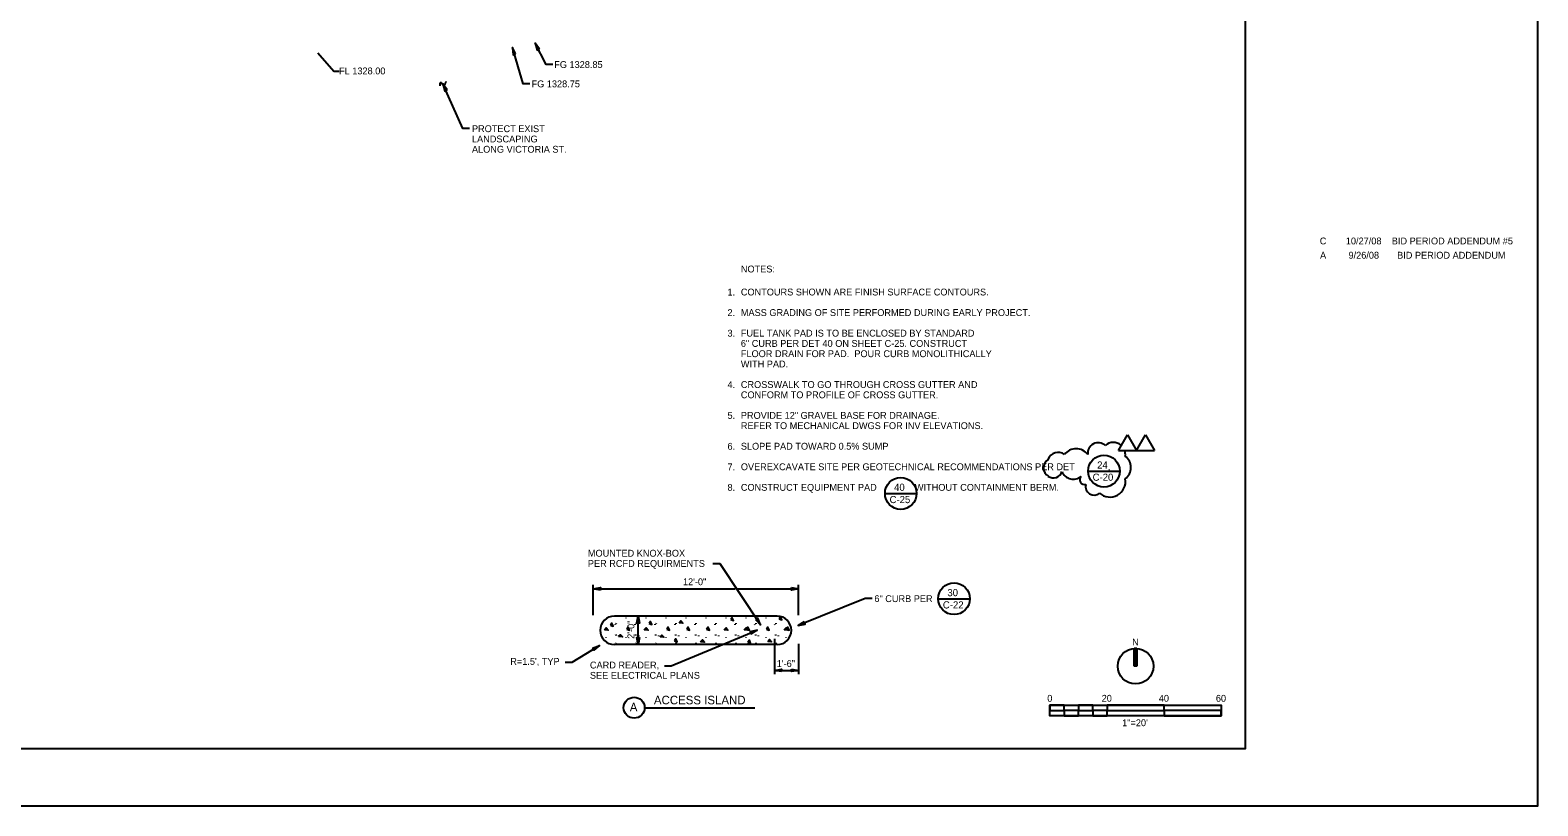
# Model space of a CAD drawing. Extents: x 0 to 3.5, y 0 to 3.39.
# Drawn here: x 1.299 to 3.5, y 0 to 1.132 of the extents above; entities that cross this region are included whole.
import ezdxf

# ---------------------------------------------------------------- set-up
doc = ezdxf.new("R2010")
doc.units = 0
for name, color, linetype in [('C-MARK', 7, 'Continuous'), ('C-PATT', 7, 'Continuous'), ('C-REVC', 7, 'Continuous'), ('C-TEXT', 7, 'Continuous'), ('G-SYMB', 7, 'Continuous'), ('G-TEXT', 7, 'Continuous'), ('G-TTLB-OTLN', 7, 'Continuous'), ('G-TTLB-VIEW', 7, 'Continuous')]:
    doc.layers.add(name, color=color, linetype=linetype)

msp = doc.modelspace()

# ---------------------------------------------------------------- linework, layer by layer
at = {"layer": 'C-MARK'}
for p, q in [((2.1211, 0.2782), (2.1211, 0.3225)), ((2.1211, 0.3167), (2.3284, 0.3167)), ((2.3318, 0.3167), (2.4209, 0.3167)), ((2.4209, 0.2782), (2.4209, 0.3225)), ((2.1868, 0.2353), (2.1868, 0.277)), ((2.2011, 0.2766), (2.2011, 0.277)), ((2.3856, 0.2436), (2.3856, 0.192)), ((2.4209, 0.2363), (2.4209, 0.192)), ((2.3856, 0.1977), (2.4209, 0.1977))]:
    msp.add_line(p, q, dxfattribs=at)
for points in [[(2.0287, 1.0536), (2.0187, 1.0536), (2.0031, 1.1065)], [(2.0623, 1.0815), (2.0523, 1.0815), (2.0364, 1.1127)], [(1.719, 1.0988), (1.7423, 1.0719), (1.7503, 1.0719)], [(1.9407, 0.9882), (1.9307, 0.9882), (1.9018, 1.0533)], [(2.2957, 0.3536), (2.3057, 0.3536), (2.3655, 0.2643)], [(2.5282, 0.3025), (2.5182, 0.3025), (2.4201, 0.2632)], [(2.2251, 0.2045), (2.2351, 0.2045), (2.3605, 0.2561)], [(2.0803, 0.2095), (2.0903, 0.2095), (2.1301, 0.234)]]:
    msp.add_lwpolyline(points, dxfattribs=at)
msp.add_open_spline([(1.8975, 1.0504), (1.8976, 1.0586), (1.9039, 1.048), (1.9064, 1.0571)], degree=2, dxfattribs=at)
at = {"layer": 'C-PATT'}
for p, q in [((2.1521, 0.277), (2.3896, 0.277)), ((2.1534, 0.264), (2.1532, 0.265)), ((2.1548, 0.2658), (2.155, 0.2664)), ((2.1585, 0.2762), (2.1585, 0.277)), ((2.1694, 0.2739), (2.1694, 0.2744)), ((2.1825, 0.264), (2.1823, 0.265)), ((2.1839, 0.2658), (2.1841, 0.2664)), ((2.1877, 0.2762), (2.1877, 0.277)), ((2.1985, 0.2739), (2.1985, 0.2744)), ((2.2117, 0.264), (2.2115, 0.265)), ((2.2131, 0.2658), (2.2133, 0.2664)), ((2.2168, 0.2762), (2.2168, 0.277)), ((2.2277, 0.2739), (2.2277, 0.2744)), ((2.2408, 0.264), (2.2406, 0.265)), ((2.2422, 0.2658), (2.2424, 0.2664)), ((2.246, 0.2762), (2.246, 0.277)), ((2.2568, 0.2739), (2.2568, 0.2744)), ((2.27, 0.264), (2.2698, 0.265)), ((2.2714, 0.2658), (2.2716, 0.2664)), ((2.2751, 0.2762), (2.2751, 0.277)), ((2.286, 0.2739), (2.286, 0.2744)), ((2.2991, 0.264), (2.2989, 0.265)), ((2.3005, 0.2658), (2.3007, 0.2664)), ((2.3043, 0.2762), (2.3043, 0.277)), ((2.3151, 0.2739), (2.3151, 0.2744)), ((2.3283, 0.264), (2.3281, 0.265)), ((2.3297, 0.2658), (2.3299, 0.2664)), ((2.3334, 0.2762), (2.3334, 0.277)), ((2.3443, 0.2739), (2.3443, 0.2744)), ((2.3574, 0.264), (2.3572, 0.265)), ((2.3588, 0.2658), (2.359, 0.2664)), ((2.3626, 0.2762), (2.3626, 0.277)), ((2.3734, 0.2739), (2.3734, 0.2744)), ((2.3866, 0.264), (2.3864, 0.265)), ((2.388, 0.2658), (2.3882, 0.2664)), ((2.3917, 0.2762), (2.3917, 0.2766)), ((2.1402, 0.2455), (2.1402, 0.246)), ((2.1544, 0.2492), (2.154, 0.2498)), ((2.1544, 0.2486), (2.1544, 0.2496)), ((2.1585, 0.2478), (2.1585, 0.2486)), ((2.1694, 0.2455), (2.1694, 0.246)), ((2.1835, 0.2492), (2.1831, 0.2498)), ((2.1835, 0.2486), (2.1835, 0.2496)), ((2.1877, 0.2478), (2.1877, 0.2486)), ((2.1985, 0.2455), (2.1985, 0.246)), ((2.2127, 0.2492), (2.2123, 0.2498)), ((2.2127, 0.2486), (2.2127, 0.2496)), ((2.2168, 0.2478), (2.2168, 0.2486)), ((2.2277, 0.2455), (2.2277, 0.246)), ((2.2418, 0.2492), (2.2414, 0.2498)), ((2.2418, 0.2486), (2.2418, 0.2496)), ((2.246, 0.2478), (2.246, 0.2486)), ((2.2568, 0.2455), (2.2568, 0.246)), ((2.271, 0.2492), (2.2706, 0.2498)), ((2.271, 0.2486), (2.271, 0.2496)), ((2.2751, 0.2478), (2.2751, 0.2486)), ((2.286, 0.2455), (2.286, 0.246)), ((2.3001, 0.2492), (2.2997, 0.2498)), ((2.3001, 0.2486), (2.3001, 0.2496)), ((2.3043, 0.2478), (2.3043, 0.2486)), ((2.3151, 0.2455), (2.3151, 0.246)), ((2.3293, 0.2492), (2.3289, 0.2498)), ((2.3293, 0.2486), (2.3293, 0.2496)), ((2.3334, 0.2478), (2.3334, 0.2486)), ((2.3443, 0.2455), (2.3443, 0.246)), ((2.3584, 0.2492), (2.358, 0.2498)), ((2.3584, 0.2486), (2.3584, 0.2496)), ((2.3626, 0.2478), (2.3626, 0.2486)), ((2.3734, 0.2455), (2.3734, 0.246)), ((2.3876, 0.2492), (2.3872, 0.2498)), ((2.3876, 0.2486), (2.3876, 0.2496)), ((2.3917, 0.2478), (2.3917, 0.2486)), ((2.4026, 0.2455), (2.4026, 0.246)), ((2.3896, 0.2353), (2.1521, 0.2353)), ((2.1534, 0.2356), (2.1532, 0.2366)), ((2.1548, 0.2374), (2.155, 0.238)), ((2.1825, 0.2356), (2.1823, 0.2366)), ((2.1839, 0.2374), (2.1841, 0.238)), ((2.2117, 0.2356), (2.2115, 0.2366)), ((2.2131, 0.2374), (2.2133, 0.238)), ((2.2408, 0.2356), (2.2406, 0.2366)), ((2.2422, 0.2374), (2.2424, 0.238)), ((2.27, 0.2356), (2.2698, 0.2366)), ((2.2714, 0.2374), (2.2716, 0.238)), ((2.2991, 0.2356), (2.2989, 0.2366)), ((2.3005, 0.2374), (2.3007, 0.238)), ((2.3283, 0.2356), (2.3281, 0.2366)), ((2.3297, 0.2374), (2.3299, 0.238)), ((2.3574, 0.2356), (2.3572, 0.2366)), ((2.3588, 0.2374), (2.359, 0.238)), ((2.3866, 0.2356), (2.3864, 0.2366)), ((2.388, 0.2374), (2.3882, 0.238))]:
    msp.add_line(p, q, dxfattribs=at)
for points in [[(2.1464, 0.2635), (2.1503, 0.2621), (2.1484, 0.2663)], [(2.2028, 0.2662), (2.2067, 0.2648), (2.2048, 0.2689)], [(2.2464, 0.2671), (2.2492, 0.2699), (2.2519, 0.2667)], [(2.3218, 0.2717), (2.3258, 0.2703), (2.3238, 0.2744)], [(2.3923, 0.2729), (2.3962, 0.2715), (2.3943, 0.2757)], [(2.1374, 0.2567), (2.1402, 0.2595), (2.1429, 0.2563)], [(2.1581, 0.247), (2.1609, 0.2497), (2.1636, 0.2466)], [(2.1701, 0.2577), (2.1741, 0.2563), (2.1721, 0.2605)], [(2.1957, 0.2567), (2.1985, 0.2595), (2.2012, 0.2563)], [(2.2186, 0.2465), (2.2214, 0.2492), (2.2241, 0.2461)], [(2.2284, 0.2577), (2.2324, 0.2563), (2.2304, 0.2605)], [(2.2397, 0.2409), (2.2436, 0.2395), (2.2417, 0.2437)], [(2.2576, 0.2577), (2.2615, 0.2563), (2.2596, 0.2605)], [(2.2778, 0.2394), (2.2806, 0.2422), (2.2833, 0.239)], [(2.2867, 0.2577), (2.2907, 0.2563), (2.2887, 0.2605)], [(2.3123, 0.2567), (2.3151, 0.2595), (2.3178, 0.2563)], [(2.3415, 0.2567), (2.3443, 0.2595), (2.347, 0.2563)], [(2.345, 0.2577), (2.349, 0.2563), (2.347, 0.2605)], [(2.3742, 0.2577), (2.3781, 0.2563), (2.3762, 0.2605)], [(2.3758, 0.2399), (2.3786, 0.2426), (2.3813, 0.2395)], [(2.3998, 0.2567), (2.4026, 0.2595), (2.4053, 0.2563)], [(2.4033, 0.2577), (2.4073, 0.2563), (2.4053, 0.2605)], [(2.347, 0.2389), (2.3509, 0.2375), (2.349, 0.2417)]]:
    msp.add_lwpolyline(points, close=True, dxfattribs=at)
for centre, start, end in [((2.1521, 0.2561), 90, 270), ((2.3896, 0.2561), 270, 90)]:
    msp.add_arc(centre, 0.0208, start, end, dxfattribs=at)
at = {"layer": 'C-REVC'}
for centre, radius, start, end in [((2.8582, 0.5145), 0.0153, 46.9529, 187.4093), ((2.8804, 0.5128), 0.0175, 50.1065, 132.5795), ((2.7996, 0.5), 0.0157, 52.944, 159.2042), ((2.826, 0.4998), 0.0212, 36.8699, 143.1301), ((2.8804, 0.5128), 0.0175, 351.5452, 19.0319), ((2.8854, 0.4937), 0.0206, 306.8699, 53.1301), ((2.793, 0.4933), 0.0146, 123.0441, 238.9396), ((2.7928, 0.4917), 0.0132, 236.0726, 342.3328), ((2.822, 0.4946), 0.018, 202.7037, 308.9639), ((2.8387, 0.4759), 0.00721, 139.0704, 281.8607), ((2.8523, 0.4659), 0.0124, 166.3609, 309.9842), ((2.8754, 0.4732), 0.0227, 228.1166, 9.9428)]:
    msp.add_arc(centre, radius, start, end, dxfattribs=at)
at = {"layer": 'C-TEXT'}
for p, q in [((2.888, 0.5187), (2.9011, 0.5413)), ((2.9011, 0.5413), (2.9141, 0.5187)), ((2.9141, 0.5187), (2.9272, 0.5413)), ((2.9272, 0.5413), (2.9402, 0.5187)), ((2.888, 0.5187), (2.9141, 0.5187)), ((2.888, 0.5187), (2.888, 0.5187)), ((2.9141, 0.5187), (2.9141, 0.5187)), ((2.9141, 0.5187), (2.9402, 0.5187)), ((2.9141, 0.5187), (2.9141, 0.5187)), ((2.9402, 0.5187), (2.9402, 0.5187)), ((2.8432, 0.4883), (2.8895, 0.4883)), ((2.5468, 0.4558), (2.5931, 0.4558)), ((2.6246, 0.3021), (2.6709, 0.3021)), ((2.1961, 0.1432), (2.3571, 0.1432))]:
    msp.add_line(p, q, dxfattribs=at)
for points in [[(2.0078, 1.0971), (2.0031, 1.1065), (2.0043, 1.096)], [(2.0428, 1.1042), (2.0364, 1.1127), (2.0395, 1.1026)], [(1.9077, 1.0445), (1.9018, 1.0533), (1.9044, 1.043)], [(2.1315, 0.3149), (2.1211, 0.3167), (2.1315, 0.3186)], [(2.4105, 0.3186), (2.4209, 0.3167), (2.4105, 0.3149)], [(2.185, 0.2665), (2.1868, 0.277), (2.1887, 0.2665)], [(2.3582, 0.272), (2.3655, 0.2643), (2.3612, 0.274)], [(2.4291, 0.2687), (2.4201, 0.2632), (2.4305, 0.2653)], [(2.1887, 0.2457), (2.1868, 0.2353), (2.185, 0.2457)], [(2.3515, 0.2505), (2.3605, 0.2561), (2.3502, 0.2539)], [(2.1202, 0.2301), (2.1301, 0.234), (2.1221, 0.227)], [(2.396, 0.1959), (2.3856, 0.1977), (2.396, 0.1996)], [(2.4105, 0.1996), (2.4209, 0.1977), (2.4105, 0.1959)]]:
    msp.add_lwpolyline(points, close=True, dxfattribs=at)
msp.add_circle((2.1808, 0.1432), 0.0153, dxfattribs=at)
for centre in [(2.8665, 0.4884), (2.5701, 0.4558), (2.6479, 0.3022)]:
    msp.add_ellipse(centre, major_axis=(0, 0.0232), ratio=0.994695, dxfattribs=at)
at = {"layer": 'G-SYMB'}
for p, q in [((2.9109, 0.2038), (2.9109, 0.2296)), ((2.9123, 0.2038), (2.9123, 0.2296)), ((2.9132, 0.2038), (2.9132, 0.2296)), ((2.9146, 0.2296), (2.9146, 0.2038)), ((2.9146, 0.2038), (2.9109, 0.2038))]:
    msp.add_line(p, q, dxfattribs=at)
for points in [[(2.7878, 0.1391), (2.8086, 0.1391), (2.8086, 0.1469), (2.7878, 0.1469)], [(2.7878, 0.1469), (3.0378, 0.1469), (3.0378, 0.1312), (2.7878, 0.1312)], [(2.8086, 0.1312), (2.8294, 0.1312), (2.8294, 0.1391), (2.8086, 0.1391)], [(2.8294, 0.1391), (2.8503, 0.1391), (2.8503, 0.1469), (2.8294, 0.1469)], [(2.8503, 0.1312), (2.8711, 0.1312), (2.8711, 0.1391), (2.8503, 0.1391)], [(2.8711, 0.1391), (2.9544, 0.1391), (2.9544, 0.1469), (2.8711, 0.1469)], [(2.9544, 0.1312), (3.0378, 0.1312), (3.0378, 0.1391), (2.9544, 0.1391)]]:
    msp.add_lwpolyline(points, close=True, dxfattribs=at)
msp.add_circle((2.9128, 0.2038), 0.026, dxfattribs=at)
msp.add_arc((2.9128, 0.2049), 0.0248, 85.7578, 94.2422, dxfattribs=at)
at = {"layer": 'G-TTLB-OTLN'}
msp.add_lwpolyline([(0, 0), (3.5, 0), (3.5, 2.5), (0, 2.5)], close=True, dxfattribs=at)
at = {"layer": 'G-TTLB-VIEW'}
msp.add_lwpolyline([(0.1667, 2.4167), (3.0729, 2.4167), (3.0729, 0.0833), (0.1667, 0.0833)], close=True, dxfattribs=at)

# ---------------------------------------------------------------- texts
at = {"layer": 'C-TEXT'}
for s, p in [('FG 1328.85', (2.0642, 1.0766)), ('FL 1328.00', (1.7501, 1.0673)), ('FG 1328.75', (2.0311, 1.0484)), ('NOTES:', (2.3366, 0.7783)), ('1.', (2.3171, 0.7446)), ('CONTOURS SHOWN ARE FINISH SURFACE CONTOURS.', (2.3366, 0.7447)), ('2.', (2.3171, 0.7146)), ('MASS GRADING OF SITE PERFORMED DURING EARLY PROJECT.', (2.3366, 0.7147)), ('3.', (2.3171, 0.6846)), ('FUEL TANK PAD IS TO BE ENCLOSED BY STANDARD', (2.3366, 0.6847)), ('6" CURB PER DET 40 ON SHEET C-25. CONSTRUCT', (2.3366, 0.6697)), ('FLOOR DRAIN FOR PAD.  POUR CURB MONOLITHICALLY', (2.3366, 0.6547)), ('WITH PAD.', (2.3366, 0.6397)), ('4.', (2.3171, 0.6096)), ('CROSSWALK TO GO THROUGH CROSS GUTTER AND ', (2.3366, 0.6097)), ('CONFORM TO PROFILE OF CROSS GUTTER.', (2.3366, 0.5947)), ('5.', (2.3171, 0.5646)), ('PROVIDE 12" GRAVEL BASE FOR DRAINAGE.', (2.3366, 0.5647)), ('REFER TO MECHANICAL DWGS FOR INV ELEVATIONS.', (2.3366, 0.5497)), ('6.', (2.3171, 0.5196)), ('SLOPE PAD TOWARD 0.5% SUMP', (2.3366, 0.5197)), ('7.', (2.3171, 0.4896)), ('OVEREXCAVATE SITE PER GEOTECHNICAL RECOMMENDATIONS PER DET             .', (2.3366, 0.4897)), ('8.', (2.3171, 0.4596)), ('CONSTRUCT EQUIPMENT PAD               WITHOUT CONTAINMENT BERM.', (2.3366, 0.4597))]:
    msp.add_text(s, height=0.01, dxfattribs=at).set_placement(p)
for s, height, rotation, p in [('PROTECT EXIST', 0.01, 360, (1.9441, 0.983)), ('LANDSCAPING', 0.01, 360, (1.9441, 0.968)), ('ALONG VICTORIA ST.', 0.01, 360, (1.9441, 0.953)), ('C-20', 0.01042, 360, (2.8501, 0.4743)), ('24', 0.01042, 360, (2.8567, 0.4921)), ('40', 0.01042, 360, (2.5603, 0.4596)), ('C-25', 0.01042, 360, (2.5537, 0.4417)), ('MOUNTED KNOX-BOX', 0.01, 360, (2.1133, 0.3636)), ('PER RCFD REQUIRMENTS', 0.01, 360, (2.1133, 0.3486)), ('12\'-0"', 0.01, 360, (2.2521, 0.3219)), ('30', 0.01042, 360, (2.6381, 0.3059)), ('6" CURB PER', 0.01, 360, (2.5315, 0.2973)), ('C-22', 0.01042, 360, (2.6315, 0.288)), ('2\'-0"', 0.01, 90, (2.1811, 0.2437)), ("R=1.5', TYP", 0.01, 360, (2, 0.2057)), ('CARD READER,', 0.01, 360, (2.1163, 0.2004)), ('1\'-6"', 0.01, 360, (2.389, 0.2026)), ('SEE ELECTRICAL PLANS', 0.01, 360, (2.1163, 0.1854)), ('ACCESS ISLAND', 0.0125, 360, (2.2097, 0.1481)), ('A', 0.0125, 360, (2.1745, 0.1378))]:
    msp.add_text(s, height=height, rotation=rotation, dxfattribs=at).set_placement(p)
at = {"layer": 'G-SYMB'}
msp.add_text('N', height=0.01, dxfattribs=at).set_placement((2.9077, 0.2341))
at = {"layer": 'G-TEXT'}
for s, p in [('C', (3.1817, 0.8192)), ('10/27/08', (3.2197, 0.8192)), ('BID PERIOD ADDENDUM #5', (3.2868, 0.8192)), ('A', (3.1821, 0.7984)), ('9/26/08', (3.2236, 0.7984)), ('BID PERIOD ADDENDUM', (3.2946, 0.7984)), ('0', (2.7839, 0.1519)), ('20', (2.8633, 0.1519)), ('40', (2.9467, 0.1519)), ('60', (3.03, 0.1519)), ('1"=20\'', (2.8932, 0.1162))]:
    msp.add_text(s, height=0.01, dxfattribs=at).set_placement(p)

doc.saveas('drawing.dxf')
